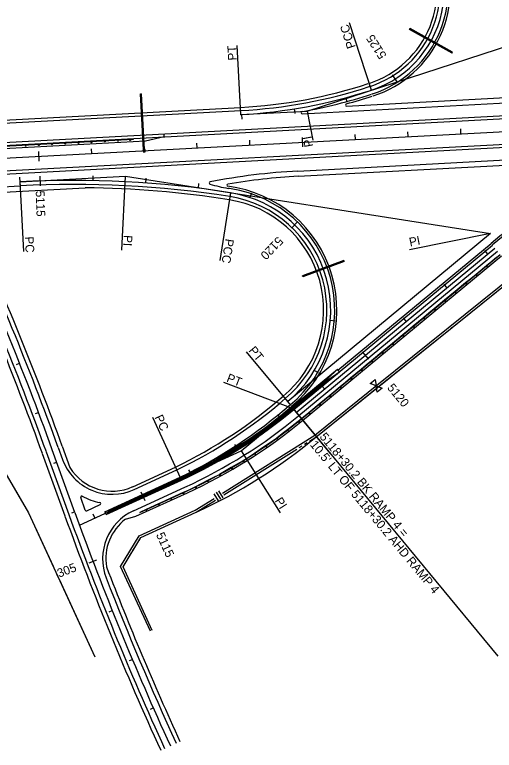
# Model space of a CAD drawing. Extents: x 192699 to 285914, y 194342 to 233219.
# Drawn here: x 257348 to 258256, y 215474 to 216867 of the extents above; entities that cross this region are included whole.
import ezdxf

# ---------------------------------------------------------------- set-up
doc = ezdxf.new("R2010")
doc.units = 0
for name, color, linetype in [('CENT LINE', 7, 'Continuous'), ('CONCRETE', 7, 'Continuous'), ('CURVE DATA', 7, 'Continuous'), ('CURVE LINE', 7, 'Continuous'), ('DRAINAGE', 7, 'Continuous'), ('R-W - CofA', 7, 'Continuous'), ('R_Proposed Guardrail', 7, 'Continuous'), ('ROAD', 7, 'Continuous'), ('SHOULDER', 7, 'Continuous'), ('STATIONING1', 7, 'Continuous'), ('STATIONING2', 7, 'Continuous')]:
    doc.layers.add(name, color=color, linetype=linetype)

msp = doc.modelspace()

# ---------------------------------------------------------------- linework, layer by layer
at = {"layer": 'CENT LINE'}
for p, q in [((255599.6, 216502.3), (261521.8, 216819.6)), ((258022.8, 216723.8), (258021.1, 216723.2)), ((257357.2, 216549.9), (257357.2, 216549.9)), ((257755.9, 216529.5), (257755.9, 216529.5)), ((257880.5, 216113.2), (258256.7, 216424.8)), ((257864.5, 216134), (257864.5, 216133.9)), ((257873.3, 216120.8), (257873.9, 216121.3)), ((257873.9, 216121.3), (257880.5, 216113.2)), ((257461.5, 215924.2), (257418.7, 216042.8)), ((257470.3, 215900.2), (257662.2, 215988.2))]:
    msp.add_line(p, q, dxfattribs=at)
for centre, radius, start, end in [((257960.8, 216913.9), 200, 288.0667, 55.5667), ((257724.9, 217631.1), 954.9, 273.0667, 288.0667), ((257459.4, 214642.8), 1909.9, 81.0667, 93.0665), ((257721, 216307.2), 225, 309.6333, 81.0667), ((252029.8, 214096.7), 5729.6, 19.85545, 24.68573), ((257264.2, 216856.2), 954.9, 294.6333, 309.6332), ((262850.5, 217870.2), 5729.6, 199.85545, 204.63334)]:
    msp.add_arc(centre, radius, start, end, dxfattribs=at)
at = {"layer": 'CONCRETE'}
for p, q in [((257868, 216120.3), (257958.4, 216195.2)), ((257940.4, 216177.7), (257958.4, 216195.2)), ((257962.2, 216190.5), (257958.4, 216195.2)), ((257875.8, 216119), (257962.2, 216190.5)), ((257941.7, 216176.1), (257962.2, 216190.5)), ((257873.2, 216122), (257940.4, 216177.7)), ((257874.5, 216120.5), (257941.7, 216176.1)), ((257518.1, 215925.4), (257660.9, 215990.9)), ((257520.6, 215920), (257663.4, 215985.5)), ((257541.7, 215934), (257661.8, 215989.1)), ((257542.5, 215932.2), (257662.6, 215987.3)), ((257481.2, 215928.5), (257472.6, 215952.5)), ((257484, 215927.4), (257509.2, 215938.9)), ((257518.1, 215925.4), (257541.7, 215934)), ((257520.6, 215920), (257542.5, 215932.2)), ((257520.6, 215920), (257518.1, 215925.4))]:
    msp.add_line(p, q, dxfattribs=at)
for centre, radius, start, end in [((257264.2, 216856.2), 951.9, 294.6333, 309.8952), ((257264.2, 216856.2), 953.9, 294.6333, 309.8949), ((257264.2, 216856.2), 955.9, 294.6333, 309.8946), ((257264.2, 216856.2), 957.9, 294.6333, 309.6332), ((257474.5, 215953.2), 2, 61.2651, 199.8555), ((257532.2, 216058.4), 118, 241.2651, 258.5669), ((257508.4, 215940.8), 2, 294.6335, 78.5669), ((257483.1, 215929.2), 2, 199.8555, 294.6335)]:
    msp.add_arc(centre, radius, start, end, dxfattribs=at)
at = {"layer": 'CURVE DATA'}
for points in [[(258022.8, 216723.8), (257981.3, 216850.9)], [(257776, 216677.5), (257769, 216808.4)], [(257901.5, 216684.2), (257911.9, 216629)], [(257550.5, 216421), (257557.6, 216560.7)], [(257357.2, 216549.9), (257364.3, 216417.9)], [(257755.9, 216529.5), (257735.8, 216401.1)], [(258248.6, 216452.1), (258095.2, 216421.2)], [(257864.5, 216134), (257786.2, 216228.5)], [(257873.3, 216120.8), (257743.7, 216169.9)], [(257873.9, 216121.3), (258262.4, 215652.2)], [(257880.6, 216113.2), (257944.4, 216036.2)], [(257662.2, 215988.2), (257609.2, 216103.8)], [(257776.5, 216040.6), (257850.1, 215923.4)]]:
    msp.add_lwpolyline(points, dxfattribs=at)
at = {"layer": 'CURVE LINE'}
for p, q in [((257901.5, 216684.2), (258408.4, 216849.6)), ((257774.2, 216677.4), (257901.5, 216684.2)), ((257357.2, 216549.9), (257557.6, 216560.7)), ((257557.6, 216560.7), (258248.6, 216452.1)), ((258248.6, 216452.1), (257864.5, 216133.9)), ((257776.5, 216040.6), (257873.9, 216121.3)), ((257662.2, 215988.2), (257776.5, 216040.6))]:
    msp.add_line(p, q, dxfattribs=at)
at = {"layer": 'DRAINAGE'}
for p, q in [((258175.5, 216793.9), (258095, 216838.5)), ((258176.5, 216795.7), (258096, 216840.2)), ((257591.5, 216611), (257585.8, 216716.9)), ((257593.5, 216611.2), (257587.8, 216717)), ((257970.9, 216401.3), (257892.2, 216372)), ((257971.6, 216399.4), (257892.9, 216370.1))]:
    msp.add_line(p, q, dxfattribs=at)
for points in [[(258095, 216838.5), (258096, 216840.2)], [(258175.5, 216793.9), (258176.5, 216795.7)], [(257585.8, 216716.9), (257587.8, 216717)], [(257971.6, 216399.4), (257970.9, 216401.3)], [(257892.9, 216370.1), (257892.2, 216372)]]:
    msp.add_lwpolyline(points, dxfattribs=at)
msp.add_lwpolyline([(257590.7, 216607), (257594.7, 216607.2), (257594.5, 216611.2), (257590.5, 216611)], close=True, dxfattribs=at)
at = {"layer": 'R-W - CofA'}
for p, q in [((257917.9, 216066.9), (258299, 216373.7)), ((258020.3, 216168.1), (258029.8, 216175.8)), ((258031.6, 216163.7), (258020.3, 216168.1)), ((258029.8, 216175.8), (258031.6, 216163.7)), ((258033.5, 216151.7), (258031.6, 216163.7)), ((258031.6, 216163.7), (258043, 216159.3)), ((258043, 216159.3), (258033.5, 216151.7)), ((257724.7, 215959.6), (257733, 215946.4)), ((257729.1, 215962.3), (257737.4, 215949.2)), ((257733.5, 215965.1), (257741.8, 215951.9)), ((257374, 215923.4), (257499, 215650.7)), ((257586.3, 215876.4), (257691.4, 215924.6)), ((257608.1, 215700.7), (257552.8, 215821.4))]:
    msp.add_line(p, q, dxfattribs=at)
for points in [[(257066.2, 216450.7), (257374, 215923.4)], [(258036.4, 216167.6), (258296.7, 216377.2), (258315.8, 216388)], [(258188.5, 216284.7), (258299, 216373.7), (258317.9, 216384.4)], [(258179.5, 216277.5), (258184.4, 216281.4)], [(258039, 216164.3), (258166.4, 216266.9)], [(258170.5, 216270.2), (258175.4, 216274.2)], [(257741.1, 215960.7), (257915.5, 216070.3), (258036.4, 216167.6)], [(257905.9, 216059.3), (257917.9, 216066.9), (257917.9, 216066.9), (258039, 216164.3)], [(257896.1, 216053.1), (257901.4, 216056.5)], [(257743.3, 215957.2), (257881.8, 216044.2)], [(257886.3, 216047), (257891.6, 216050.3)], [(257342.4, 215977.5), (257374, 215923.4), (257420.3, 215822.3)], [(257604.4, 215699), (257548.1, 215821.7), (257583.4, 215879.6), (257689.4, 215928.2), (257725.3, 215950.8)], [(257583.6, 215871.9), (257586.3, 215876.4), (257691.4, 215924.6), (257691.4, 215924.6), (257727.5, 215947.3)], [(257552.8, 215821.4), (257586.3, 215876.4)], [(257577.6, 215862), (257580.8, 215867.4)], [(257608.1, 215700.7), (257552.8, 215821.4), (257568.8, 215847.7)], [(257571.5, 215852.2), (257574.8, 215857.5)], [(257422.4, 215817.8), (257424.9, 215812.3)], [(257427, 215807.8), (257429.5, 215802.3)], [(257431.6, 215797.7), (257499, 215650.7)]]:
    msp.add_lwpolyline(points, dxfattribs=at)
msp.add_arc((257264.2, 216856.2), 1024.9, 294.6333, 309.6332, dxfattribs=at)
at = {"layer": 'R_Proposed Guardrail'}
for p, q in [((257630.6, 216635.2), (257630.3, 216641.2)), ((257595, 216627.3), (257015.2, 216596.2)), ((257572.4, 216630.1), (257023.2, 216600.6)), ((257630.6, 216635.2), (257595, 216627.3)), ((257890.4, 216101.2), (258266.6, 216412.8)), ((257892.7, 216098.5), (258268.9, 216410.1)), ((257577.2, 215916.8), (257674.5, 215961.4)), ((257584.8, 215924.1), (257673, 215964.6)), ((257557.6, 215911.4), (257577.2, 215916.8))]:
    msp.add_line(p, q, dxfattribs=at)
for points in [[(258260.5, 216407.7), (258250.6, 216399.5)], [(258240.7, 216391.3), (258220.9, 216374.9)], [(258250.6, 216399.5), (258240.7, 216391.3)], [(258211, 216366.7), (258201.1, 216358.6)], [(258220.9, 216374.9), (258211, 216366.7)], [(258201.1, 216358.6), (258181.3, 216342.2)], [(258171.4, 216334), (258161.5, 216325.8)], [(258181.3, 216342.2), (258171.4, 216334)], [(258161.5, 216325.8), (258141.7, 216309.4)], [(258141.7, 216309.4), (258131.9, 216301.2)], [(258122, 216293), (258102.2, 216276.6)], [(258131.9, 216301.2), (258122, 216293)], [(258092.3, 216268.4), (258082.4, 216260.2)], [(258102.2, 216276.6), (258092.3, 216268.4)], [(258082.4, 216260.2), (258062.6, 216243.8)], [(258062.6, 216243.8), (258052.7, 216235.6)], [(258042.8, 216227.4), (258023, 216211.1)], [(258052.7, 216235.6), (258042.8, 216227.4)], [(258023, 216211.1), (258013.1, 216202.9)], [(258003.2, 216194.7), (257983.4, 216178.3)], [(258013.1, 216202.9), (258003.2, 216194.7)], [(257973.6, 216170.1), (257963.7, 216161.9)], [(257983.4, 216178.3), (257973.6, 216170.1)], [(257963.7, 216161.9), (257943.9, 216145.5)], [(257943.9, 216145.5), (257934, 216137.3)], [(257924.1, 216129.1), (257904.3, 216112.7)], [(257934, 216137.3), (257924.1, 216129.1)], [(257904.3, 216112.7), (257894.4, 216104.5)], [(257894.4, 216104.5), (257890.4, 216101.2), (257889.9, 216100.8), (257884.4, 216096.5)], [(257884.4, 216096.5), (257864.1, 216080.7)], [(257853.9, 216072.9), (257843.8, 216065)], [(257864.1, 216080.7), (257853.9, 216072.9)], [(257843.8, 216065), (257840.4, 216062.4), (257822.7, 216050.4)], [(257812, 216043.1), (257801.4, 216035.9)], [(257822.7, 216050.4), (257812, 216043.1)], [(257801.4, 216035.9), (257788.6, 216027.2), (257779.8, 216022.1)], [(257768.7, 216015.5), (257757.7, 216009)], [(257779.8, 216022.1), (257768.7, 216015.5)], [(257757.7, 216009), (257735.5, 215996)], [(257724.1, 215990.1), (257712.6, 215984.3)], [(257735.5, 215996), (257734.6, 215995.4), (257724.1, 215990.1)], [(257689.7, 215972.7), (257678.7, 215967.2), (257678.2, 215967)], [(257712.6, 215984.3), (257689.7, 215972.7)], [(257666.6, 215961.6), (257643.2, 215950.9)], [(257678.2, 215967), (257673, 215964.6), (257673, 215964.6), (257666.6, 215961.6)], [(257631.5, 215945.5), (257619.8, 215940.2)], [(257643.2, 215950.9), (257631.5, 215945.5)], [(257619.8, 215940.2), (257596.5, 215929.5)], [(257596.5, 215929.5), (257584.8, 215924.1)]]:
    msp.add_lwpolyline(points, dxfattribs=at)
for centre, radius in [((257518.1, 216626.4), 0.75), ((257543.1, 216627.7), 0.75), ((257566.3, 216628.9), 0.75), ((257368.3, 216618.4), 0.75), ((257393.3, 216619.7), 0.75), ((257418.2, 216621), 0.75), ((257443.2, 216622.4), 0.75), ((257468.2, 216623.7), 0.75), ((257493.1, 216625), 0.75), ((258241.4, 216390.5), 1.13), ((258221.6, 216374.1), 1.13), ((258201.8, 216357.7), 1.13), ((258182, 216341.3), 1.13), ((258162.3, 216324.9), 1.13), ((258142.5, 216308.5), 1.13), ((258122.7, 216292.1), 1.13), ((258102.9, 216275.7), 1.13), ((258083.1, 216259.3), 1.13), ((258063.3, 216243), 1.13), ((258043.5, 216226.6), 1.13), ((258023.7, 216210.2), 1.13), ((258004, 216193.8), 1.13), ((257984.2, 216177.4), 1.13), ((257964.4, 216161), 1.13), ((257944.6, 216144.6), 1.13), ((257924.8, 216128.2), 1.13), ((257905, 216111.8), 1.13), ((257885.1, 216095.6), 1.13), ((257864.8, 216079.9), 1.13), ((257844.5, 216064.1), 1.13), ((257823.3, 216049.4), 1.13), ((257802, 216035), 1.13), ((257780.4, 216021.1), 1.13), ((257758.2, 216008.1), 1.13), ((257736.1, 215995), 1.13), ((257690.2, 215971.7), 1.13), ((257713.1, 215983.3), 1.13), ((257667, 215960.6), 1.13), ((257643.7, 215949.9), 1.13), ((257620.3, 215939.1), 1.13), ((257597, 215928.4), 1.13)]:
    msp.add_circle(centre, radius, dxfattribs=at)
for radius in [980.9, 984.4]:
    msp.add_arc((257264.2, 216856.2), radius, 294.6333, 309.6332, dxfattribs=at)
at = {"layer": 'ROAD'}
for p, q in [((255599.6, 216532.4), (261521.8, 216849.6)), ((255599.6, 216472.3), (261521.8, 216789.6)), ((258020.5, 216730.9), (258018.7, 216730.4)), ((257892.1, 216679.2), (258590.7, 216716.7)), ((258025.1, 216716.7), (258023.4, 216716.1)), ((257201.7, 216654.3), (257775.6, 216685)), ((257883.7, 216570.6), (258627.5, 216610.5)), ((255599.6, 216448.2), (257357.6, 216542.4)), ((257875.8, 216119), (258252, 216430.5)), ((257885.3, 216107.4), (258261.5, 216419)), ((257873.9, 216121.3), (257880.5, 216113.2)), ((257430, 216046.9), (257438.1, 216024.4)), ((257407.4, 216038.7), (257450.3, 215920.1)), ((257573.8, 215967.5), (257654.7, 216004.6)), ((257518.1, 215925.4), (257660.9, 215990.9)), ((257520.6, 215920), (257663.4, 215985.5)), ((257572.4, 215927.2), (257669.7, 215971.8))]:
    msp.add_line(p, q, dxfattribs=at)
for centre, radius, start, end in [((257960.8, 216913.9), 192.5, 288.0667, 28.2264), ((257960.8, 216913.9), 207.5, 288.0667, 28.4767), ((257724.9, 217631.1), 947.4, 273.0667, 288.0667), ((257724.9, 217631.1), 962.4, 279.9743, 288.0667), ((257892, 216681.2), 2, 99.9743, 273.0667), ((258778.8, 215794.4), 826, 100.5228, 129.6333), ((257946.9, 215390.3), 1182, 93.0667, 101.1891), ((257459.4, 214642.8), 1902.4, 81.0667, 93.0665), ((257717.9, 216547.9), 2, 101.1891, 251.8688), ((257785, 216752.7), 217.5, 251.8688, 261.2259), ((257459.4, 214642.8), 1917.4, 81.0667, 81.2259), ((257721, 216307.2), 232.5, 309.6333, 81.0667), ((257721, 216307.2), 217.5, 309.6333, 81.0667), ((252029.8, 214096.7), 5741.6, 19.85545, 24.68573), ((252029.8, 214096.7), 5717.6, 19.8555, 24.6857), ((257246.5, 216846.9), 936, 295.8567, 310.9325), ((257246.5, 216846.9), 951, 295.8567, 310.9325), ((257264.2, 216856.2), 957.9, 294.6333, 309.677), ((257264.2, 216856.2), 972.9, 294.6333, 309.6332), ((257532.2, 216058.4), 100, 199.8555, 294.6334), ((262850.5, 217870.2), 5741.6, 199.85545, 204.63334), ((257614.1, 215836.3), 100, 114.6334, 201.227), ((262850.5, 217870.2), 5717.6, 201.227, 204.6333)]:
    msp.add_arc(centre, radius, start, end, dxfattribs=at)
at = {"layer": 'SHOULDER'}
for p, q in [((255599.9, 216526.4), (261522.1, 216843.7)), ((255599.3, 216478.3), (261521.5, 216795.6)), ((257976, 216693.7), (258590.2, 216726.6)), ((257201.4, 216660.2), (257775.3, 216691)), ((257884.2, 216560.6), (258549.9, 216596.3)), ((255600.1, 216438.3), (257481.2, 216539)), ((257959.6, 216193.6), (258249.4, 216433.6)), ((257437.5, 216049.6), (257452.2, 216009)), ((257399.9, 216036), (257442.7, 215917.4)), ((257571.3, 215972.9), (257652.2, 216010))]:
    msp.add_line(p, q, dxfattribs=at)
for centre, radius, start, end in [((257960.8, 216913.9), 186.5, 288.0667, 28.2264), ((257960.8, 216913.9), 211.5, 288.0667, 23.5057), ((257724.9, 217631.1), 941.4, 273.0667, 288.0667), ((257724.9, 217631.1), 966.4, 285.0204, 288.0667), ((257975.9, 216695.7), 2, 105.0204, 273.0667), ((258778.8, 215794.4), 830, 105.9675, 129.6333), ((257946.9, 215390.3), 1172, 93.0667, 99.633), ((257751.1, 216543.8), 2, 99.633, 262.7388), ((257459.4, 214642.8), 1896.4, 81.0667, 89.3407), ((257721, 216307.2), 236.5, 309.6333, 82.7388), ((257721, 216307.2), 211.5, 309.6333, 81.0667), ((252029.8, 214096.7), 5749.6, 19.85545, 24.18004), ((252029.8, 214096.7), 5709.6, 19.8555, 24.18), ((257246.5, 216846.9), 930, 295.8567, 310.9325), ((257246.5, 216846.9), 955, 307.3253, 310.9325), ((257532.2, 216058.4), 94, 211.6957, 294.6334), ((262850.5, 217870.2), 5749.6, 199.85545, 204.63334), ((257614.1, 215836.3), 94, 126.9412, 189.2888), ((262850.5, 217870.2), 5709.6, 201.0319, 204.6333)]:
    msp.add_arc(centre, radius, start, end, dxfattribs=at)
at = {"layer": 'STATIONING1'}
for points in [[(258091.4, 216644.8), (258091.9, 216635.9)], [(258191.3, 216650.2), (258191.8, 216641.2)], [(257791.9, 216628.8), (257792.3, 216619.8)], [(257891.7, 216634.1), (257892.7, 216616.2)], [(257991.6, 216639.5), (257992.1, 216630.5)], [(257492.3, 216612.7), (257492.8, 216603.8)], [(257592.1, 216618.1), (257592.6, 216609.1)], [(257692, 216623.4), (257692.5, 216614.5)], [(257392.4, 216607.4), (257393.4, 216589.4)]]:
    msp.add_lwpolyline(points, dxfattribs=at)
at = {"layer": 'STATIONING2'}
for points in [[(258143.6, 216812.7), (258135.8, 216817.1)], [(258072.7, 216737.4), (258063.1, 216752.6)], [(257977.3, 216700.8), (257974.9, 216709.4)], [(257878.6, 216679.5), (257877.2, 216688.4)], [(257778.3, 216668.6), (257777.8, 216677.6)], [(257356.7, 216558.9), (257357.7, 216540.9)], [(257356.7, 216558.9), (257357.2, 216549.9)], [(257395, 216560.6), (257395.6, 216542.6)], [(257495.5, 216561.3), (257495.3, 216552.3)], [(257595.9, 216556.8), (257595.2, 216547.8)], [(257695.8, 216547), (257694.7, 216538.1)], [(257795.9, 216528.9), (257793, 216520.4)], [(257883.9, 216475.2), (257871.4, 216462.3)], [(258236.7, 216419.8), (258242.4, 216412.9)], [(257940.3, 216388.8), (257931.9, 216385.7)], [(258159.7, 216356.1), (258165.4, 216349.1)], [(258082.7, 216292.3), (258088.4, 216285.3)], [(257954.1, 216286.6), (257945.1, 216287.4)], [(258005.7, 216228.5), (258017.1, 216214.6)], [(257351.2, 216204.4), (257356.7, 216206.6)], [(257922.6, 216188.4), (257914.8, 216193)], [(257928.6, 216164.7), (257934.4, 216157.8)], [(257870.3, 216127), (257858.8, 216140.9)], [(257870.3, 216127), (257864.5, 216133.9)], [(257387.1, 216111.2), (257392.7, 216113.3)], [(257844.9, 216109.5), (257850.4, 216102.4)], [(257763.6, 216052.9), (257768.4, 216045.3)], [(257421.5, 216017.3), (257427.2, 216019.4)], [(257676.9, 216005.1), (257680.8, 215997)], [(257586.3, 215963.3), (257593.8, 215946.9)], [(257455.5, 215923.3), (257461.1, 215925.3)], [(257495.4, 215921.6), (257499.1, 215913.4)], [(257488.4, 215828.7), (257503.4, 215834.4)], [(257526.7, 215736.2), (257532.3, 215738.4)], [(257564.8, 215643.6), (257570.3, 215645.9)], [(257604.4, 215551.7), (257609.9, 215554.1)]]:
    msp.add_lwpolyline(points, dxfattribs=at)

# ---------------------------------------------------------------- texts
at = {"layer": 'CURVE DATA'}
for s, rotation, p in [('PCC', 108.0667, (257993.3, 216805.6)), ('PT', 93.0667, (257768.1, 216780.4)), ('PI', 100.5667, (257912.9, 216617.5)), ('PC', 273.0665, (257366.8, 216446.2)), ('PI', 267.0666, (257554.2, 216449.6)), ('PI', 11.3831, (258096.1, 216427.5)), ('PCC', 261.0667, (257746.5, 216443.2)), ('PT', 309.6333, (257789.6, 216230.3)), ('PT', 339.2283, (257747.4, 216172.3)), ('PC', 294.6333, (257612, 216104.5)), ('5118+30.2 BK RAMP 4 =', 309.6333, (257923.8, 216066.8)), ("10.5' LT OF 5118+30.2 AHD RAMP 4", 309.6333, (257905.7, 216051.9)), ('PI', 302.1333, (257839.1, 215946.2))]:
    msp.add_text(s, height=16.5, rotation=rotation, dxfattribs=at).set_placement(p)
at = {"layer": 'STATIONING2'}
for s, rotation, p in [('5125', 122.3904, (258052.3, 216789.4)), ('5115', 271.9209, (257387.4, 216533.1)), ('5120', 225.8761, (257845.7, 216447.7)), ('5120', 309.6333, (258051.7, 216159.7)), ('5115', 294.6333, (257614.8, 215881.9)), ('305', 20.8433, (257431.7, 215800.5))]:
    msp.add_text(s, height=16.5, rotation=rotation, dxfattribs=at).set_placement(p)

doc.saveas('drawing.dxf')
